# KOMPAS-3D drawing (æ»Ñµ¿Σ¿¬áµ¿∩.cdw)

Referenced files: Спецификация.cdw
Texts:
  Буксы Спецификация
  Текст на чертеже
  Размерные надписи
  Шероховатость
  Линия-выноска #1
  Линия-выноска #2
  Линия-выноска #3
  Отклонения формы и база
  Заголовок таблицы
  Ячейка таблицы
  Стрелка вида
  Обозначение изменения
  Фигурная скобка
  Номер узла
  Марка координационной оси
  VRCB
  Выносная надпись
  Обозначение узла
  Марка/позиционное обозначение с линией-выноской
  Марка/позиционное обозначение на линии
  Марка/позиционное обозначение без линии-выноски
  Буксы
  ХХХХ.ХХ.ХХ.00 СБ
  Документация
  Сборочный чертеж.
  Детали
  Корпус левый
  Кронштейн левый
  Кронштейн правый
  Крышка
  Кольцо
  Вал
  Болт М10х35.58
  ГОСТ 7798-70
  Болт М16х95.58
  Гайка М16.5
  ГОСТ 5915-70
  Кольцо СГ 103-84-7
  Стандартные изделия
  ГОСТ 6418-81
Dimensions and other numbers on the sheet: 7; 4; 1:1; 1; 2; 3; 5; 6; 8; 9; 0; 10; 11; 12; 13; 14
